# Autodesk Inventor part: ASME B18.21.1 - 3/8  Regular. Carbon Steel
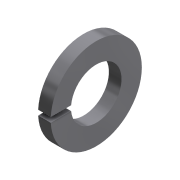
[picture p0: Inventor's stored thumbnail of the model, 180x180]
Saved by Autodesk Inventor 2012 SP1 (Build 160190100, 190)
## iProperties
Created: 2000-06
Part Number: ASME B18.21.1 - 3/8  Regular. Carbon Steel
Material: Stainless Steel, Austenitic
Description: Helical Spring Lock Washer
Document SubType Name: Standard Catalog Part
Standard: ASME B18.21.1 - 3/8  Regular. Carbon Steel
Designer: Ron
Density: 1 g/cm^3
Control State: 0
Master: False
Checked Out: False
Shininess: 60.0
Length Units: 11272
Angle Units: 11279
Time Units: 11290
Mass Units: 11286
Length Display Precision: 3
Angle Display Precision: 2
Density: 0.0
Volumn: 0.0
Area: 0.0
PropertySet Name: Model Information
Author: Ron
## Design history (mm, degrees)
node "Base1"
body "Solid1"
